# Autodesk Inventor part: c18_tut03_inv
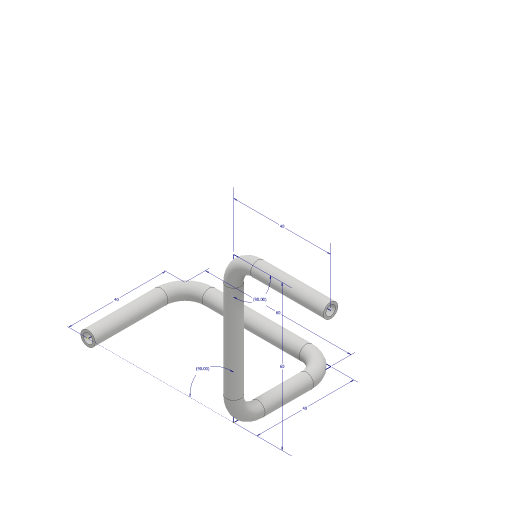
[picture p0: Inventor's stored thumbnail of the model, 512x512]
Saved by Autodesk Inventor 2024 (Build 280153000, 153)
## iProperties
Created: 2017-06
Part Number: c18_tut03_inv
Material: Generic
Document SubType Name: Modeling
Designer: CADCIM 00
Density: 1 g/cm^3
Appearance: Default
Author: CADCIM 00
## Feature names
1. Sweep1
## Parameters: d6 = 90 deg, d8 = 90 deg, d14 = 6 mm, d15 = 4 mm, d16 = 0, d17 = 0
